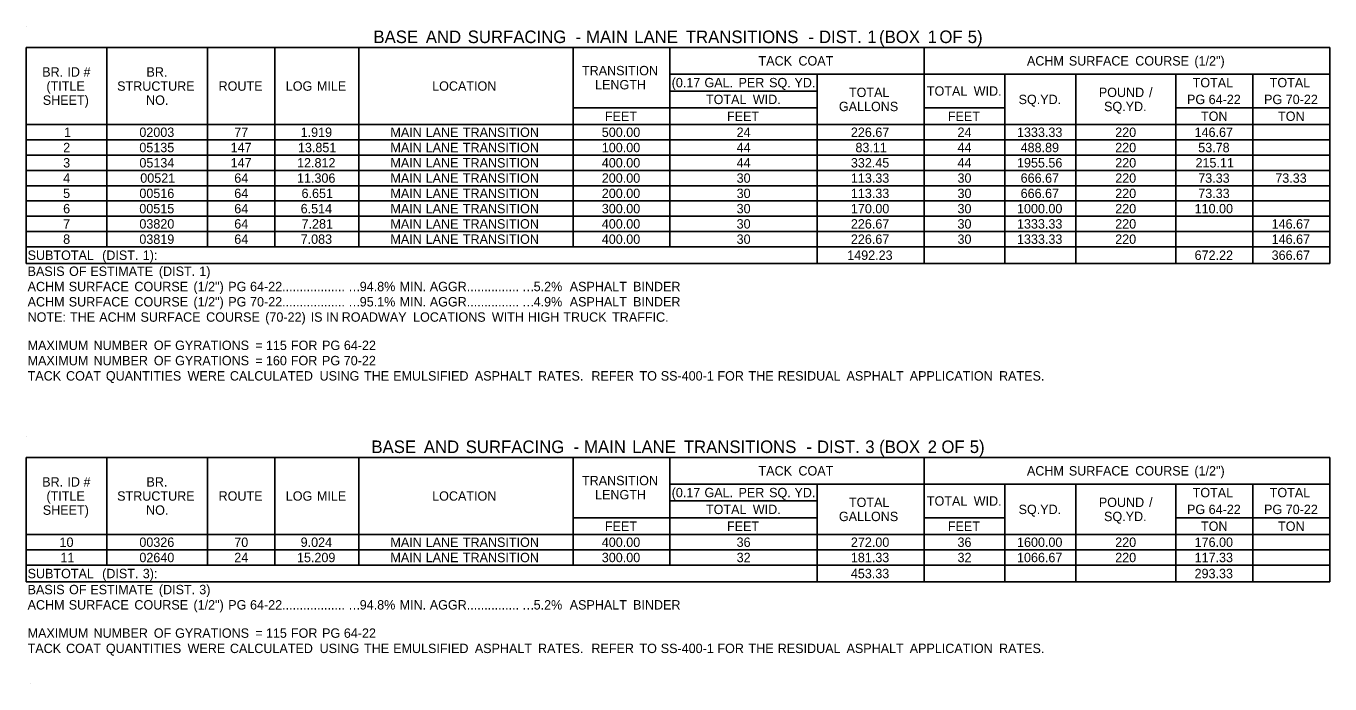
# Model space of a CAD drawing. Extents: x 544255 to 1930787, y -1947044 to 596640.
# Drawn here: x 550278 to 551111, y -1946516 to -1946096 of the extents above; entities that cross this region are included whole.
import ezdxf

# ---------------------------------------------------------------- set-up
doc = ezdxf.new("R2010")
doc.units = 0
doc.layers.add('Default', color=7, linetype='Continuous')

msp = doc.modelspace()

# ---------------------------------------------------------------- linework, layer by layer
at = {"layer": 'Default'}
for p, q in [((550277.82, -1946095.91), (550277.82, -1946095.91)), ((550277.82, -1946109.56), (551110.96, -1946109.56)), ((550277.82, -1946247.52), (550277.82, -1946109.56)), ((550329.5, -1946236.8), (550329.5, -1946109.56)), ((550393.85, -1946236.8), (550393.85, -1946109.56)), ((550436.75, -1946236.8), (550436.75, -1946109.56)), ((550490.37, -1946236.8), (550490.37, -1946109.56)), ((550627.36, -1946236.8), (550627.36, -1946109.56)), ((550689.27, -1946236.8), (550689.27, -1946109.56)), ((550689.27, -1946126.62), (550689.27, -1946109.56)), ((550851.61, -1946247.52), (550851.61, -1946109.56)), ((551110.96, -1946247.52), (551110.96, -1946109.56)), ((550689.27, -1946126.62), (551110.96, -1946126.62)), ((550783.36, -1946137.35), (550783.36, -1946126.62)), ((550783.36, -1946247.52), (550783.36, -1946126.62)), ((550903.28, -1946126.62), (550948.62, -1946126.62)), ((550903.28, -1946247.52), (550903.28, -1946126.62)), ((550948.62, -1946247.52), (550948.62, -1946126.62)), ((551012.48, -1946247.52), (551012.48, -1946126.62)), ((551061.72, -1946247.52), (551061.72, -1946126.62)), ((550689.27, -1946137.35), (550783.36, -1946137.35)), ((550627.36, -1946148.07), (550689.27, -1946148.07)), ((550627.36, -1946148.07), (550783.36, -1946148.07)), ((550783.36, -1946158.8), (550783.36, -1946148.07)), ((550851.61, -1946148.07), (550903.28, -1946148.07)), ((550851.61, -1946158.8), (550851.61, -1946148.07)), ((550903.28, -1946158.8), (550903.28, -1946148.07)), ((551012.48, -1946148.07), (551110.96, -1946148.07)), ((550277.82, -1946158.8), (550903.28, -1946158.8)), ((550627.36, -1946158.8), (550689.27, -1946158.8)), ((550783.36, -1946158.8), (550903.28, -1946158.8)), ((550903.28, -1946158.8), (551110.96, -1946158.8)), ((550903.28, -1946158.8), (550948.62, -1946158.8)), ((550277.82, -1946168.55), (551110.96, -1946168.55)), ((550277.82, -1946178.3), (551110.96, -1946178.3)), ((550277.82, -1946188.05), (551110.96, -1946188.05)), ((550277.82, -1946197.8), (551110.96, -1946197.8)), ((550277.82, -1946207.55), (551110.96, -1946207.55)), ((550277.82, -1946217.3), (551110.96, -1946217.3)), ((550277.82, -1946227.05), (551110.96, -1946227.05)), ((550277.82, -1946236.8), (551110.96, -1946236.8)), ((550277.82, -1946236.8), (551110.96, -1946236.8)), ((550277.82, -1946247.52), (551110.96, -1946247.52)), ((550277.82, -1946357.62), (550277.82, -1946357.62)), ((550277.82, -1946371.27), (551110.96, -1946371.27)), ((550277.82, -1946450.74), (550277.82, -1946371.27)), ((550329.5, -1946440.01), (550329.5, -1946371.27)), ((550393.85, -1946440.01), (550393.85, -1946371.27)), ((550436.75, -1946440.01), (550436.75, -1946371.27)), ((550490.37, -1946440.01), (550490.37, -1946371.27)), ((550627.36, -1946440.01), (550627.36, -1946371.27)), ((550689.27, -1946440.01), (550689.27, -1946371.27)), ((550689.27, -1946388.34), (550689.27, -1946371.27)), ((550851.61, -1946450.74), (550851.61, -1946371.27)), ((551110.96, -1946450.74), (551110.96, -1946371.27)), ((550689.27, -1946388.34), (551110.96, -1946388.34)), ((550783.36, -1946399.06), (550783.36, -1946388.34)), ((550783.36, -1946450.74), (550783.36, -1946388.34)), ((550903.28, -1946388.34), (550948.62, -1946388.34)), ((550903.28, -1946450.74), (550903.28, -1946388.34)), ((550948.62, -1946450.74), (550948.62, -1946388.34)), ((551012.48, -1946450.74), (551012.48, -1946388.34)), ((551061.72, -1946450.74), (551061.72, -1946388.34)), ((550689.27, -1946399.06), (550783.36, -1946399.06)), ((550627.36, -1946409.79), (550689.27, -1946409.79)), ((550627.36, -1946409.79), (550783.36, -1946409.79)), ((550783.36, -1946420.51), (550783.36, -1946409.79)), ((550851.61, -1946409.79), (550903.28, -1946409.79)), ((550851.61, -1946420.51), (550851.61, -1946409.79)), ((550903.28, -1946420.51), (550903.28, -1946409.79)), ((551012.48, -1946409.79), (551110.96, -1946409.79)), ((550277.82, -1946420.51), (550783.36, -1946420.51)), ((550277.82, -1946420.51), (551110.96, -1946420.51)), ((550783.36, -1946420.51), (550903.28, -1946420.51)), ((550903.28, -1946420.51), (551110.96, -1946420.51)), ((550277.82, -1946430.26), (551110.96, -1946430.26)), ((550277.82, -1946430.26), (551110.96, -1946430.26)), ((550277.82, -1946440.01), (551110.96, -1946440.01)), ((550277.82, -1946440.01), (551110.96, -1946440.01)), ((550277.82, -1946450.74), (551110.96, -1946450.74)), ((550280.78, -1946515.84), (550280.78, -1946515.84))]:
    msp.add_line(p, q, dxfattribs=at)

# ---------------------------------------------------------------- texts
for s, height, p in [('BASE', 8, (550499.78, -1946106.74)), (' AND', 8, (550530.28, -1946106.74)), (' SURFACING', 8, (550557.05, -1946106.74)), (' MAIN', 8, (550632.67, -1946106.74)), (' LANE', 8, (550663.44, -1946106.74)), (' TRANSITIONS', 8, (550696.42, -1946106.74)), (' DIST.', 8, (550781.49, -1946106.74)), (' 1', 8, (550812.39, -1946106.74)), (' (BOX', 8, (550819.9, -1946106.74)), (' 1', 8, (550850.93, -1946106.74)), (' OF', 8, (550858.44, -1946106.74)), (' 5)', 8, (550876.55, -1946106.74)), (' -', 8, (550625.93, -1946106.74)), (' -', 8, (550774.74, -1946106.74)), ('TACK', 6, (550745.85, -1946121.09)), (' COAT', 6, (550769.12, -1946121.09)), ('ACHM', 6, (550917.35, -1946121.09)), (' SURFACE', 6, (550941.9, -1946121.09)), (' COURSE', 6, (550984.34, -1946121.09)), (' (1/2")', 6, (551022.12, -1946121.09)), ('BR.', 6, (550288.14, -1946128.18)), (' ID', 6, (550302, -1946128.18)), (' #', 6, (550312.29, -1946128.18)), ('BR.', 6, (550354.74, -1946128.18)), ('TRANSITION', 6, (550633.04, -1946127.32)), ('(TITLE', 6, (550290.83, -1946137.18)), ('STRUCTURE', 6, (550336.03, -1946137.18)), ('ROUTE', 6, (550400.83, -1946137.18)), ('LOG', 6, (550443.76, -1946137.18)), (' MILE', 6, (550461.42, -1946137.18)), ('LOCATION', 6, (550537.31, -1946137.18)), ('LENGTH', 6, (550641.4, -1946136.32)), ('(0.17', 6, (550690.34, -1946134.99)), (' GAL.', 6, (550709.07, -1946134.99)), (' PER', 6, (550730.84, -1946134.99)), (' SQ.', 6, (550750.37, -1946134.99)), (' YD.', 6, (550766.57, -1946134.99)), ('TOTAL', 6, (551023.26, -1946134.99)), ('TOTAL', 6, (551072.5, -1946134.99)), ('SHEET)', 6, (550288.5, -1946146.18)), ('NO.', 6, (550354.51, -1946146.18)), ('TOTAL', 6, (550712.28, -1946145.71)), (' WID.', 6, (550739.97, -1946145.71)), ('TOTAL', 6, (550803.64, -1946141.21)), ('TOTAL', 6, (550853.42, -1946140.35)), (' WID.', 6, (550881.11, -1946140.35)), ('SQ.YD.', 6, (550912.03, -1946145.71)), ('POUND', 6, (550963.29, -1946141.21)), (' /', 6, (550993.15, -1946141.21)), ('PG', 6, (551019.63, -1946145.71)), (' 64-22', 6, (551031.24, -1946145.71)), ('PG', 6, (551068.87, -1946145.71)), (' 70-22', 6, (551080.48, -1946145.71)), ('FEET', 6, (550647.69, -1946156.44)), ('FEET', 6, (550725.69, -1946156.44)), ('GALLONS', 6, (550797.2, -1946150.21)), ('FEET', 6, (550866.82, -1946156.44)), ('SQ.YD.', 6, (550966.63, -1946150.21)), ('TON', 6, (551028.59, -1946156.44)), ('TON', 6, (551077.83, -1946156.44)), ('1', 6, (550302.1, -1946166.67)), ('02003', 6, (550350.21, -1946166.67)), ('77', 6, (550410.83, -1946166.67)), ('1.919', 6, (550453.26, -1946166.67)), ('MAIN', 6, (550510.63, -1946166.67)), (' LANE', 6, (550530.91, -1946166.67)), (' TRANSITION', 6, (550554.69, -1946166.67)), ('500.00', 6, (550645.7, -1946166.67)), ('24', 6, (550731.86, -1946166.67)), ('226.67', 6, (550804.86, -1946166.67)), ('24', 6, (550872.99, -1946166.67)), ('1333.33', 6, (550911, -1946166.67)), ('220', 6, (550973.76, -1946166.67)), ('146.67', 6, (551024.48, -1946166.67)), ('2', 6, (550301.55, -1946176.42)), ('05135', 6, (550350.19, -1946176.42)), ('147', 6, (550408.5, -1946176.42)), ('13.851', 6, (550451.52, -1946176.42)), ('MAIN', 6, (550510.63, -1946176.42)), (' LANE', 6, (550530.91, -1946176.42)), (' TRANSITION', 6, (550554.69, -1946176.42)), ('100.00', 6, (550645.7, -1946176.42)), ('44', 6, (550731.86, -1946176.42)), ('83.11', 6, (550807.77, -1946176.42)), ('44', 6, (550872.99, -1946176.42)), ('488.89', 6, (550913.32, -1946176.42)), ('220', 6, (550973.76, -1946176.42)), ('53.78', 6, (551026.8, -1946176.42)), ('3', 6, (550301.52, -1946186.17)), ('05134', 6, (550350.23, -1946186.17)), ('147', 6, (550408.5, -1946186.17)), ('12.812', 6, (550450.97, -1946186.17)), ('MAIN', 6, (550510.63, -1946186.17)), (' LANE', 6, (550530.91, -1946186.17)), (' TRANSITION', 6, (550554.69, -1946186.17)), ('400.00', 6, (550645.7, -1946186.17)), ('44', 6, (550731.86, -1946186.17)), ('332.45', 6, (550804.84, -1946186.17)), ('44', 6, (550872.99, -1946186.17)), ('1955.56', 6, (550911, -1946186.17)), ('220', 6, (550973.76, -1946186.17)), ('215.11', 6, (551025.06, -1946186.17)), ('4', 6, (550301.53, -1946195.92)), ('00521', 6, (550350.79, -1946195.92)), ('64', 6, (550410.84, -1946195.92)), ('11.306', 6, (550450.94, -1946195.92)), ('MAIN', 6, (550510.63, -1946195.92)), (' LANE', 6, (550530.91, -1946195.92)), (' TRANSITION', 6, (550554.69, -1946195.92)), ('200.00', 6, (550645.7, -1946195.92)), ('30', 6, (550731.86, -1946195.92)), ('113.33', 6, (550804.86, -1946195.92)), ('30', 6, (550872.99, -1946195.92)), ('666.67', 6, (550913.33, -1946195.92)), ('220', 6, (550973.76, -1946195.92)), ('73.33', 6, (551026.81, -1946195.92)), ('73.33', 6, (551076.05, -1946195.92)), ('5', 6, (550301.5, -1946205.67)), ('00516', 6, (550350.21, -1946205.67)), ('64', 6, (550410.84, -1946205.67)), ('6.651', 6, (550453.85, -1946205.67)), ('MAIN', 6, (550510.63, -1946205.67)), (' LANE', 6, (550530.91, -1946205.67)), (' TRANSITION', 6, (550554.69, -1946205.67)), ('200.00', 6, (550645.7, -1946205.67)), ('30', 6, (550731.86, -1946205.67)), ('113.33', 6, (550804.86, -1946205.67)), ('30', 6, (550872.99, -1946205.67)), ('666.67', 6, (550913.33, -1946205.67)), ('220', 6, (550973.76, -1946205.67)), ('73.33', 6, (551026.81, -1946205.67)), ('6', 6, (550301.52, -1946215.42)), ('00515', 6, (550350.19, -1946215.42)), ('64', 6, (550410.84, -1946215.42)), ('6.514', 6, (550453.28, -1946215.42)), ('MAIN', 6, (550510.63, -1946215.42)), (' LANE', 6, (550530.91, -1946215.42)), (' TRANSITION', 6, (550554.69, -1946215.42)), ('300.00', 6, (550645.7, -1946215.42)), ('30', 6, (550731.86, -1946215.42)), ('170.00', 6, (550804.87, -1946215.42)), ('30', 6, (550872.99, -1946215.42)), ('1000.00', 6, (550911.01, -1946215.42)), ('220', 6, (550973.76, -1946215.42)), ('110.00', 6, (551024.49, -1946215.42)), ('7', 6, (550301.52, -1946225.17)), ('03820', 6, (550350.22, -1946225.17)), ('64', 6, (550410.84, -1946225.17)), ('7.281', 6, (550453.85, -1946225.17)), ('MAIN', 6, (550510.63, -1946225.17)), (' LANE', 6, (550530.91, -1946225.17)), (' TRANSITION', 6, (550554.69, -1946225.17)), ('400.00', 6, (550645.7, -1946225.17)), ('30', 6, (550731.86, -1946225.17)), ('226.67', 6, (550804.86, -1946225.17)), ('30', 6, (550872.99, -1946225.17)), ('1333.33', 6, (550911, -1946225.17)), ('220', 6, (550973.76, -1946225.17)), ('146.67', 6, (551073.72, -1946225.17)), ('8', 6, (550301.52, -1946234.92)), ('03819', 6, (550350.21, -1946234.92)), ('64', 6, (550410.84, -1946234.92)), ('7.083', 6, (550453.27, -1946234.92)), ('MAIN', 6, (550510.63, -1946234.92)), (' LANE', 6, (550530.91, -1946234.92)), (' TRANSITION', 6, (550554.69, -1946234.92)), ('400.00', 6, (550645.7, -1946234.92)), ('30', 6, (550731.86, -1946234.92)), ('226.67', 6, (550804.86, -1946234.92)), ('30', 6, (550872.99, -1946234.92)), ('1333.33', 6, (550911, -1946234.92)), ('220', 6, (550973.76, -1946234.92)), ('146.67', 6, (551073.72, -1946234.92)), ('SUBTOTAL', 6, (550278.8, -1946245.16)), (' (DIST.', 6, (550324.19, -1946245.16)), (' 1):', 6, (550350.16, -1946245.16)), ('1492.23', 6, (550802.52, -1946245.16)), ('672.22', 6, (551024.5, -1946245.16)), ('366.67', 6, (551073.71, -1946245.16)), ('BASIS', 6, (550278.8, -1946255.4)), (' OF', 6, (550303.06, -1946255.4)), (' ESTIMATE', 6, (550316.64, -1946255.4)), (' (DIST.', 6, (550360.45, -1946255.4)), (' 1)', 6, (550386.26, -1946255.4)), ('ACHM', 6, (550278.8, -1946265.15)), (' SURFACE', 6, (550302.85, -1946265.15)), (' COURSE', 6, (550344.8, -1946265.15)), (' (1/2")', 6, (550382.55, -1946265.15)), (' PG', 6, (550404.78, -1946265.15)), (' 64-22..................', 6, (550418.7, -1946265.15)), ('94.8%', 6, (550491.02, -1946265.15)), (' MIN.', 6, (550514.26, -1946265.15)), (' AGGR...............', 6, (550533.55, -1946265.15)), ('5.2%', 6, (550602.15, -1946265.15)), ('  ASPHALT', 6, (550620.73, -1946265.15)), (' BINDER', 6, (550663.43, -1946265.15)), ('…', 6, (550483.62, -1946265.15)), ('…', 6, (550594.75, -1946265.15)), ('ACHM', 6, (550278.8, -1946274.9)), (' SURFACE', 6, (550302.85, -1946274.9)), (' COURSE', 6, (550344.8, -1946274.9)), (' (1/2")', 6, (550382.55, -1946274.9)), (' PG', 6, (550404.78, -1946274.9)), (' 70-22..................', 6, (550418.7, -1946274.9)), ('…', 6, (550483.62, -1946274.9)), ('95.1%', 6, (550491.02, -1946274.9)), (' MIN.', 6, (550514.26, -1946274.9)), (' AGGR...............', 6, (550533.55, -1946274.9)), ('…', 6, (550594.75, -1946274.9)), ('4.9%', 6, (550602.15, -1946274.9)), ('  ASPHALT', 6, (550620.73, -1946274.9)), (' BINDER', 6, (550663.43, -1946274.9)), ('NOTE:', 6, (550278.8, -1946284.65)), (' THE', 6, (550303.68, -1946284.65)), (' ACHM', 6, (550322.33, -1946284.65)), (' SURFACE', 6, (550348.72, -1946284.65)), (' COURSE', 6, (550390.66, -1946284.65)), (' (70-22)', 6, (550428.41, -1946284.65)), (' IS', 6, (550457.45, -1946284.65)), (' IN', 6, (550467.26, -1946284.65)), (' ROADWAY', 6, (550477.28, -1946284.65)), (' LOCATIONS', 6, (550522.87, -1946284.65)), (' WITH', 6, (550573.2, -1946284.65)), (' HIGH', 6, (550596.27, -1946284.65)), (' TRUCK', 6, (550618.88, -1946284.65)), (' TRAFFIC.', 6, (550650.07, -1946284.65)), ('MAXIMUM', 6, (550278.8, -1946302.69)), (' NUMBER', 6, (550318.68, -1946302.69)), (' OF', 6, (550357.23, -1946302.69)), (' GYRATIONS', 6, (550370.82, -1946302.69)), (' =', 6, (550422.09, -1946302.69)), (' 115', 6, (550428.84, -1946302.69)), (' FOR', 6, (550444.82, -1946302.69)), (' PG', 6, (550464.73, -1946302.69)), (' 64-22', 6, (550478.64, -1946302.69)), ('MAXIMUM', 6, (550278.8, -1946312.44)), (' NUMBER', 6, (550318.68, -1946312.44)), (' OF', 6, (550357.23, -1946312.44)), (' GYRATIONS', 6, (550370.82, -1946312.44)), (' =', 6, (550422.09, -1946312.44)), (' 160', 6, (550428.84, -1946312.44)), (' FOR', 6, (550444.75, -1946312.44)), (' PG', 6, (550464.66, -1946312.44)), (' 70-22', 6, (550478.58, -1946312.44)), ('TACK', 6, (550278.8, -1946322.19)), (' COAT', 6, (550301.14, -1946322.19)), (' QUANTITIES', 6, (550326.59, -1946322.19)), (' WERE', 6, (550378.79, -1946322.19)), (' CALCULATED', 6, (550405.82, -1946322.19)), (' USING', 6, (550463.14, -1946322.19)), (' THE', 6, (550491.5, -1946322.19)), (' EMULSIFIED', 6, (550510.14, -1946322.19)), (' ASPHALT', 6, (550562.33, -1946322.19)), (' RATES.', 6, (550602.7, -1946322.19)), ('  REFER', 6, (550634.58, -1946322.19)), (' TO', 6, (550667.54, -1946322.19)), (' SS-400-1', 6, (550681.14, -1946322.19)), (' FOR', 6, (550717.33, -1946322.19)), (' THE', 6, (550737.24, -1946322.19)), (' RESIDUAL', 6, (550755.89, -1946322.19)), (' ASPHALT', 6, (550799.85, -1946322.19)), (' APPLICATION', 6, (550840.22, -1946322.19)), (' RATES.', 6, (550897.3, -1946322.19)), ('BASE', 8, (550498.49, -1946368.45)), (' AND', 8, (550528.99, -1946368.45)), (' SURFACING', 8, (550555.76, -1946368.45)), (' -', 8, (550624.64, -1946368.45)), (' MAIN', 8, (550631.38, -1946368.45)), (' LANE', 8, (550662.15, -1946368.45)), (' TRANSITIONS', 8, (550695.13, -1946368.45)), (' -', 8, (550773.46, -1946368.45)), (' DIST.', 8, (550780.2, -1946368.45)), (' 3', 8, (550811.1, -1946368.45)), (' (BOX', 8, (550819.94, -1946368.45)), (' 2', 8, (550850.97, -1946368.45)), (' OF', 8, (550859.73, -1946368.45)), (' 5)', 8, (550877.84, -1946368.45)), ('BR.', 6, (550288.14, -1946389.89)), (' ID', 6, (550302, -1946389.89)), (' #', 6, (550312.29, -1946389.89)), ('BR.', 6, (550354.74, -1946389.89)), ('TRANSITION', 6, (550633.04, -1946389.03)), ('TACK', 6, (550745.85, -1946382.8)), (' COAT', 6, (550769.12, -1946382.8)), ('ACHM', 6, (550917.35, -1946382.8)), (' SURFACE', 6, (550941.9, -1946382.8)), (' COURSE', 6, (550984.34, -1946382.8)), (' (1/2")', 6, (551022.12, -1946382.8)), ('LENGTH', 6, (550641.4, -1946398.03)), ('(0.17', 6, (550690.34, -1946396.7)), (' GAL.', 6, (550709.07, -1946396.7)), (' PER', 6, (550730.84, -1946396.7)), (' SQ.', 6, (550750.37, -1946396.7)), (' YD.', 6, (550766.57, -1946396.7)), ('TOTAL', 6, (551023.26, -1946396.7)), ('TOTAL', 6, (551072.5, -1946396.7)), ('(TITLE', 6, (550290.83, -1946398.89)), ('STRUCTURE', 6, (550336.03, -1946398.89)), ('ROUTE', 6, (550400.83, -1946398.89)), ('LOG', 6, (550443.76, -1946398.89)), (' MILE', 6, (550461.42, -1946398.89)), ('LOCATION', 6, (550537.31, -1946398.89)), ('TOTAL', 6, (550803.64, -1946402.92)), ('TOTAL', 6, (550853.42, -1946402.06)), (' WID.', 6, (550881.11, -1946402.06)), ('POUND', 6, (550963.29, -1946402.92)), (' /', 6, (550993.15, -1946402.92)), ('SHEET)', 6, (550288.5, -1946407.89)), ('NO.', 6, (550354.51, -1946407.89)), ('TOTAL', 6, (550712.28, -1946407.42)), (' WID.', 6, (550739.97, -1946407.42)), ('GALLONS', 6, (550797.2, -1946411.92)), ('SQ.YD.', 6, (550912.03, -1946407.42)), ('SQ.YD.', 6, (550966.63, -1946411.92)), ('PG', 6, (551019.63, -1946407.42)), (' 64-22', 6, (551031.24, -1946407.42)), ('PG', 6, (551068.87, -1946407.42)), (' 70-22', 6, (551080.48, -1946407.42)), ('FEET', 6, (550647.69, -1946418.15)), ('FEET', 6, (550725.69, -1946418.15)), ('FEET', 6, (550866.82, -1946418.15)), ('TON', 6, (551028.59, -1946418.15)), ('TON', 6, (551077.83, -1946418.15)), ('10', 6, (550299.2, -1946428.39)), ('00326', 6, (550350.21, -1946428.39)), ('70', 6, (550410.84, -1946428.39)), ('9.024', 6, (550453.28, -1946428.39)), ('MAIN', 6, (550510.63, -1946428.39)), (' LANE', 6, (550530.91, -1946428.39)), (' TRANSITION', 6, (550554.69, -1946428.39)), ('400.00', 6, (550645.7, -1946428.39)), ('36', 6, (550731.85, -1946428.39)), ('272.00', 6, (550804.87, -1946428.39)), ('36', 6, (550872.98, -1946428.39)), ('1600.00', 6, (550911.01, -1946428.39)), ('220', 6, (550973.76, -1946428.39)), ('176.00', 6, (551024.49, -1946428.39)), ('11', 6, (550299.77, -1946438.14)), ('02640', 6, (550350.22, -1946438.14)), ('24', 6, (550410.84, -1946438.14)), ('15.209', 6, (550450.93, -1946438.14)), ('MAIN', 6, (550510.63, -1946438.14)), (' LANE', 6, (550530.91, -1946438.14)), (' TRANSITION', 6, (550554.69, -1946438.14)), ('300.00', 6, (550645.7, -1946438.14)), ('32', 6, (550731.88, -1946438.14)), ('181.33', 6, (550804.86, -1946438.14)), ('32', 6, (550873.01, -1946438.14)), ('1066.67', 6, (550911, -1946438.14)), ('220', 6, (550973.76, -1946438.14)), ('117.33', 6, (551024.48, -1946438.14)), ('SUBTOTAL', 6, (550278.8, -1946448.37)), (' (DIST.', 6, (550324.19, -1946448.37)), (' 3):', 6, (550350.16, -1946448.37)), ('453.33', 6, (550804.85, -1946448.37)), ('293.33', 6, (551024.47, -1946448.37)), ('BASIS', 6, (550278.8, -1946458.61)), (' OF', 6, (550303.06, -1946458.61)), (' ESTIMATE', 6, (550316.64, -1946458.61)), (' (DIST.', 6, (550360.45, -1946458.61)), (' 3)', 6, (550386.26, -1946458.61)), ('ACHM', 6, (550278.8, -1946468.36)), (' SURFACE', 6, (550302.85, -1946468.36)), (' COURSE', 6, (550344.8, -1946468.36)), (' (1/2")', 6, (550382.55, -1946468.36)), (' PG', 6, (550404.78, -1946468.36)), (' 64-22..................', 6, (550418.7, -1946468.36)), ('…', 6, (550483.62, -1946468.36)), ('94.8%', 6, (550491.02, -1946468.36)), (' MIN.', 6, (550514.26, -1946468.36)), (' AGGR...............', 6, (550533.55, -1946468.36)), ('…', 6, (550594.75, -1946468.36)), ('5.2%', 6, (550602.15, -1946468.36)), ('  ASPHALT', 6, (550620.73, -1946468.36)), (' BINDER', 6, (550663.43, -1946468.36)), ('MAXIMUM', 6, (550278.8, -1946486.4)), (' NUMBER', 6, (550318.68, -1946486.4)), (' OF', 6, (550357.23, -1946486.4)), (' GYRATIONS', 6, (550370.82, -1946486.4)), (' =', 6, (550422.09, -1946486.4)), (' 115', 6, (550428.84, -1946486.4)), (' FOR', 6, (550444.82, -1946486.4)), (' PG', 6, (550464.73, -1946486.4)), (' 64-22', 6, (550478.64, -1946486.4)), ('TACK', 6, (550278.8, -1946496.15)), (' COAT', 6, (550301.14, -1946496.15)), (' QUANTITIES', 6, (550326.59, -1946496.15)), (' WERE', 6, (550378.79, -1946496.15)), (' CALCULATED', 6, (550405.82, -1946496.15)), (' USING', 6, (550463.14, -1946496.15)), (' THE', 6, (550491.5, -1946496.15)), (' EMULSIFIED', 6, (550510.14, -1946496.15)), (' ASPHALT', 6, (550562.33, -1946496.15)), (' RATES.', 6, (550602.7, -1946496.15)), ('  REFER', 6, (550634.58, -1946496.15)), (' TO', 6, (550667.54, -1946496.15)), (' SS-400-1', 6, (550681.14, -1946496.15)), (' FOR', 6, (550717.33, -1946496.15)), (' THE', 6, (550737.24, -1946496.15)), (' RESIDUAL', 6, (550755.89, -1946496.15)), (' ASPHALT', 6, (550799.85, -1946496.15)), (' APPLICATION', 6, (550840.22, -1946496.15)), (' RATES.', 6, (550897.3, -1946496.15))]:
    msp.add_text(s, height=height, dxfattribs=at).set_placement(p)

doc.saveas('drawing.dxf')
